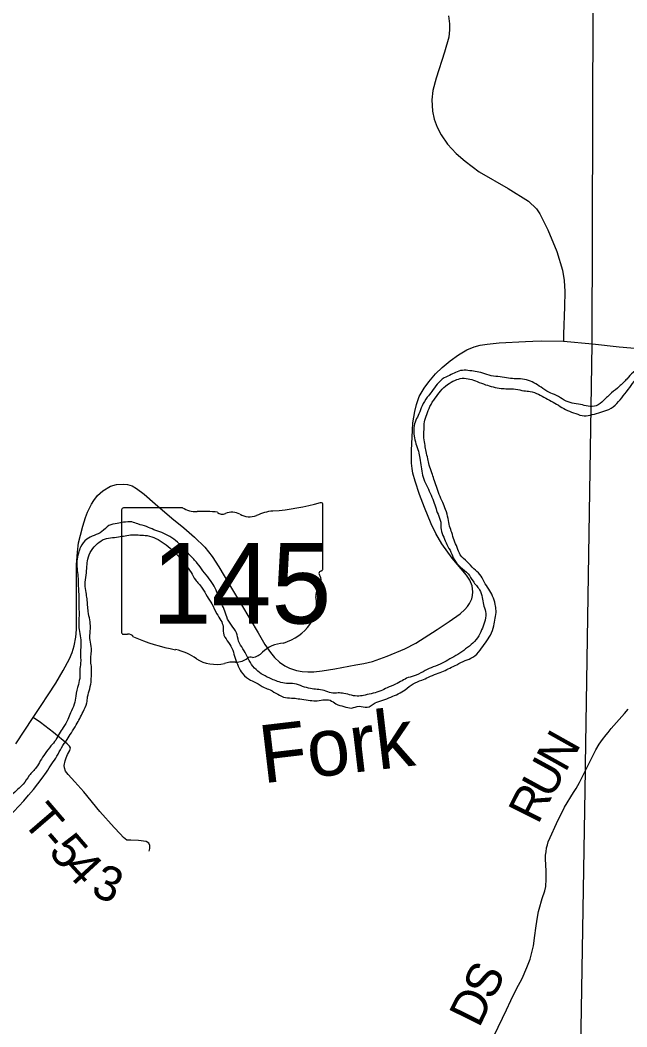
# Model space of a CAD drawing. Extents: x -10.5 to 40.6, y -3.2 to 22.
# Drawn here: x -7.105 to -6.111, y 17.758 to 19.405 of the extents above; entities that cross this region are included whole.
import ezdxf

# ---------------------------------------------------------------- set-up
doc = ezdxf.new("R2010")
doc.units = 0
for name, color, linetype in [('GM_X_Major_River', 7, 'Continuous'), ('GM_X_Major_River_Text', 7, 'Continuous'), ('GM_X_State_Location', 7, 'Continuous'), ('GM_X_State_Route', 7, 'Continuous'), ('GM_X_State_Shield', 7, 'Continuous'), ('GM_X_Township_Road', 7, 'Continuous'), ('GM_X_Township_Road_Text', 7, 'Continuous'), ('GM_X_Township_Text', 7, 'Continuous')]:
    doc.layers.add(name, color=color, linetype=linetype)

msp = doc.modelspace()

# ---------------------------------------------------------------- linework, layer by layer
at = {"layer": 'GM_X_Major_River'}
for points in [[(-5.8589, 19.0727), (-5.8485, 19.0607), (-5.838, 19.0484), (-5.8313, 19.0356), (-5.8292, 19.0219), (-5.8305, 19.0098), (-5.8341, 18.9972), (-5.8411, 18.9845), (-5.8511, 18.9714), (-5.863, 18.9602), (-5.8761, 18.9474), (-5.8891, 18.9358), (-5.8989, 18.9273), (-5.9104, 18.9168), (-5.922, 18.9052), (-5.934, 18.8952), (-5.9471, 18.887), (-5.9602, 18.8784), (-5.9734, 18.8706), (-5.9858, 18.865), (-5.9982, 18.8599), (-6.0111, 18.8577), (-6.0258, 18.8529), (-6.0386, 18.85), (-6.0503, 18.8479), (-6.0628, 18.8458), (-6.0757, 18.8426), (-6.0873, 18.8374), (-6.1008, 18.8285), (-6.1113, 18.8176), (-6.1236, 18.8053), (-6.1363, 18.7948), (-6.1493, 18.7824), (-6.1613, 18.7739), (-6.1746, 18.7729), (-6.1872, 18.7761), (-6.2009, 18.7781), (-6.2138, 18.7832), (-6.2265, 18.7906), (-6.2391, 18.7961), (-6.2518, 18.8042), (-6.2633, 18.8112), (-6.2755, 18.8163), (-6.2888, 18.818), (-6.2983, 18.8182), (-6.3116, 18.8203), (-6.326, 18.8219), (-6.3405, 18.8247), (-6.3535, 18.829), (-6.3653, 18.8307), (-6.3774, 18.832), (-6.3891, 18.8295), (-6.3989, 18.8248), (-6.4102, 18.8193), (-6.4218, 18.8092), (-6.4303, 18.7973), (-6.4381, 18.7877), (-6.4466, 18.7739), (-6.4517, 18.7605), (-6.4568, 18.7501), (-6.46, 18.7379), (-6.4594, 18.7243), (-6.4565, 18.7118), (-6.4525, 18.6993), (-6.4504, 18.688), (-6.4479, 18.6739), (-6.4458, 18.6603), (-6.441, 18.6471), (-6.4347, 18.6343), (-6.4291, 18.6211), (-6.4247, 18.6083), (-6.4204, 18.5962), (-6.416, 18.5833), (-6.4154, 18.5712), (-6.411, 18.5587), (-6.4058, 18.5467), (-6.3992, 18.5343), (-6.394, 18.5222), (-6.3836, 18.5098), (-6.3712, 18.4987), (-6.3631, 18.4867), (-6.3526, 18.4728), (-6.3482, 18.4603), (-6.3461, 18.4486), (-6.3425, 18.4373), (-6.3434, 18.4232), (-6.3477, 18.4102), (-6.3536, 18.3976), (-6.3632, 18.3856), (-6.3752, 18.3759), (-6.3879, 18.367), (-6.4011, 18.3595), (-6.4135, 18.3525), (-6.4281, 18.3465), (-6.4413, 18.3406), (-6.456, 18.3331), (-6.4692, 18.3291)], [(-6.4358, 18.3297), (-6.423, 18.3352), (-6.4113, 18.3396), (-6.4012, 18.3447), (-6.3895, 18.3502), (-6.376, 18.3569), (-6.3636, 18.3624), (-6.3512, 18.3741), (-6.3427, 18.386), (-6.3346, 18.3987), (-6.3292, 18.4139), (-6.3267, 18.4261), (-6.3254, 18.4387), (-6.3268, 18.4489), (-6.3312, 18.4625), (-6.3374, 18.4738), (-6.3448, 18.4858), (-6.3519, 18.4979), (-6.3619, 18.5072), (-6.3727, 18.5184), (-6.3839, 18.53), (-6.3891, 18.542), (-6.3942, 18.5537), (-6.3978, 18.5662), (-6.4014, 18.5768), (-6.4039, 18.5892), (-6.408, 18.604), (-6.4127, 18.6157), (-6.4183, 18.6289), (-6.4231, 18.6417), (-6.4271, 18.6538), (-6.4303, 18.664), (-6.435, 18.6768), (-6.4371, 18.687), (-6.44, 18.6991), (-6.4417, 18.709), (-6.4434, 18.7211), (-6.4433, 18.7348), (-6.4427, 18.7473), (-6.4388, 18.7596), (-6.4337, 18.7726), (-6.4252, 18.786), (-6.4163, 18.7979), (-6.4051, 18.8084), (-6.3927, 18.8154), (-6.381, 18.8187), (-6.3681, 18.8174), (-6.3562, 18.8134), (-6.3425, 18.8083), (-6.3303, 18.8047), (-6.317, 18.8023), (-6.3067, 18.8017), (-6.2934, 18.8012), (-6.2797, 18.7984), (-6.2695, 18.7971), (-6.2561, 18.7927), (-6.2439, 18.7861), (-6.232, 18.7799), (-6.2205, 18.7728), (-6.2086, 18.7662), (-6.1949, 18.7611), (-6.1812, 18.7572), (-6.1679, 18.7593), (-6.1539, 18.7634), (-6.1407, 18.7678), (-6.1276, 18.7775), (-6.1172, 18.7902), (-6.1065, 18.8037), (-6.0968, 18.8168), (-6.083, 18.8254), (-6.058, 18.8288), (-6.0425, 18.834), (-6.0293, 18.8377), (-6.0157, 18.8421), (-6.0056, 18.8464), (-5.9916, 18.8501), (-5.9814, 18.8533), (-5.9682, 18.8589), (-5.9554, 18.8655), (-5.9431, 18.8734), (-5.9292, 18.882), (-5.9168, 18.8913), (-5.9083, 18.9009), (-5.8952, 18.9125), (-5.8828, 18.9226), (-5.8694, 18.9354), (-5.8571, 18.947), (-5.8455, 18.959), (-5.8355, 18.9717), (-5.8282, 18.9851), (-5.8216, 18.9981), (-5.818, 19.01), (-5.8175, 19.0229), (-5.82, 19.0358), (-5.8255, 19.0486), (-5.8325, 19.0602), (-5.8426, 19.0722)], [(-6.4692, 18.3291), (-6.4793, 18.324), (-6.4902, 18.3181), (-6.5038, 18.3122), (-6.514, 18.3074), (-6.5268, 18.3034), (-6.5396, 18.3005), (-6.5498, 18.2988), (-6.562, 18.3001), (-6.5746, 18.3033), (-6.5841, 18.3039), (-6.5951, 18.3041), (-6.6069, 18.3077), (-6.6183, 18.3098), (-6.6293, 18.3111), (-6.6423, 18.3147), (-6.6556, 18.319), (-6.6686, 18.3196), (-6.6807, 18.322), (-6.6903, 18.3256), (-6.7156, 18.3396), (-6.7256, 18.3505), (-6.733, 18.3636), (-6.7397, 18.3761), (-6.7468, 18.3888), (-6.7504, 18.4021), (-6.7586, 18.4148), (-6.7664, 18.4284), (-6.7704, 18.4405), (-6.7759, 18.4525), (-6.7811, 18.4657), (-6.787, 18.4785), (-6.7948, 18.4906), (-6.8053, 18.5037), (-6.8146, 18.5164), (-6.8266, 18.5291), (-6.8366, 18.5381), (-6.8471, 18.5508), (-6.8597, 18.5597), (-6.8724, 18.5663), (-6.8854, 18.571), (-6.8976, 18.5761), (-6.9117, 18.5804), (-6.9216, 18.5837), (-6.9353, 18.5831), (-6.9455, 18.5814), (-6.9591, 18.5777), (-6.9707, 18.568), (-6.9834, 18.5617), (-6.9955, 18.5554), (-7.0055, 18.5424), (-7.0091, 18.5328), (-7.0115, 18.5198), (-7.0113, 18.5073), (-7.01, 18.4944), (-7.0094, 18.4819), (-7.0088, 18.469), (-7.0082, 18.4565), (-7.0083, 18.4443), (-7.0081, 18.4299), (-7.0086, 18.417), (-7.0073, 18.4045), (-7.0051, 18.3908), (-7.0053, 18.3779), (-7.0058, 18.3657), (-7.0053, 18.3563), (-7.0066, 18.3437), (-7.0067, 18.3312), (-7.0092, 18.3178), (-7.0134, 18.2988), (-7.0158, 18.2854), (-7.022, 18.2713), (-7.0264, 18.2606), (-7.0341, 18.2475), (-7.0408, 18.2371), (-7.0463, 18.2268), (-7.0541, 18.2172), (-7.0637, 18.2048), (-7.0715, 18.1926), (-7.0781, 18.1822), (-7.0896, 18.1687), (-7.0996, 18.1548), (-7.1134, 18.1417), (-7.125, 18.1301), (-7.1358, 18.12), (-7.1447, 18.1074), (-7.1536, 18.0973), (-7.1667, 18.0849), (-7.1783, 18.0737), (-7.1906, 18.061)], [(-7.1956, 18.0366), (-7.0613, 18.1745), (-7.0524, 18.1879), (-7.0443, 18.2006), (-7.0366, 18.2144), (-7.0277, 18.2279), (-7.0207, 18.2386), (-7.0126, 18.2517), (-7.0016, 18.2731), (-6.9954, 18.2877), (-6.994, 18.2976), (-6.9905, 18.3109), (-6.9881, 18.3254), (-6.9878, 18.3357), (-6.9876, 18.3452), (-6.9889, 18.355), (-6.9884, 18.3668), (-6.9878, 18.3767), (-6.9899, 18.3903), (-6.9901, 18.4013), (-6.9895, 18.4108), (-6.9905, 18.4237), (-6.993, 18.437), (-6.994, 18.4476), (-6.9949, 18.4578), (-6.9966, 18.4684), (-6.998, 18.4813), (-6.9964, 18.4969), (-6.9951, 18.511), (-6.9938, 18.5228), (-6.9876, 18.537), (-6.9779, 18.5482), (-6.9663, 18.5556), (-6.9534, 18.5581), (-6.9405, 18.5598), (-6.9296, 18.5615), (-6.9182, 18.5629), (-6.9087, 18.5623), (-6.8966, 18.5613), (-6.8821, 18.5566), (-6.869, 18.5485), (-6.856, 18.5381), (-6.8455, 18.5277), (-6.8351, 18.5145), (-6.8246, 18.5011), (-6.8175, 18.489), (-6.8063, 18.4755), (-6.7985, 18.462), (-6.7907, 18.4496), (-6.7828, 18.4338), (-6.7758, 18.4225), (-6.7722, 18.4127), (-6.7717, 18.4021), (-6.7654, 18.3893), (-6.7579, 18.3773), (-6.7535, 18.364), (-6.7488, 18.3508), (-6.7425, 18.3384), (-6.7305, 18.3268), (-6.7183, 18.3206), (-6.7049, 18.3129), (-6.6953, 18.3088), (-6.67, 18.2964), (-6.6571, 18.2955), (-6.6469, 18.2941), (-6.6328, 18.2921), (-6.621, 18.2911), (-6.6089, 18.2925), (-6.5971, 18.2919), (-6.5876, 18.286), (-6.5746, 18.2817), (-6.562, 18.2793), (-6.5496, 18.2821), (-6.5366, 18.2805), (-6.5235, 18.2875), (-6.511, 18.2919), (-6.4975, 18.2971), (-6.4742, 18.3093), (-6.4611, 18.319), (-6.4471, 18.3249), (-6.4358, 18.3297)]]:
    msp.add_spline(points, degree=3, dxfattribs=at)
at = {"layer": 'GM_X_State_Route'}
for points in [[(-6.4035, 19.4118), (-6.4014, 19.3986), (-6.4014, 19.3891), (-6.4029, 19.3769), (-6.4099, 19.3525), (-6.4237, 19.3096), (-6.4288, 19.2894), (-6.4303, 19.2746), (-6.4296, 19.2557), (-6.4268, 19.2426), (-6.422, 19.2299), (-6.4153, 19.2172), (-6.4049, 19.2017), (-6.3906, 19.1865), (-6.3759, 19.1739), (-6.3532, 19.1565), (-6.3056, 19.1293), (-6.2723, 19.1084), (-6.2594, 19.096), (-6.2537, 19.0881), (-6.2488, 19.078), (-6.2406, 19.0616), (-6.2261, 19.0262), (-6.2169, 18.9957), (-6.2141, 18.9786), (-6.2127, 18.9608), (-6.2133, 18.9358), (-6.2149, 18.8907), (-6.2151, 18.8795)], [(-6.2151, 18.8795), (-6.1676, 18.875), (-6.1239, 18.8703), (-6.1049, 18.8687), (-6.0917, 18.868), (-6.0781, 18.8683), (-6.0676, 18.8699), (-6.0607, 18.8715), (-6.053, 18.874), (-6.0416, 18.8797), (-6.0326, 18.8851), (-6.0226, 18.8927), (-6.0091, 18.9037), (-6, 18.9114)], [(-7.1116, 18.2209), (-7.0832, 18.2636), (-7.0703, 18.2834), (-7.0588, 18.3008), (-7.046, 18.3202), (-7.0338, 18.3408), (-7.0237, 18.36), (-7.0196, 18.37), (-7.0159, 18.3811), (-7.0133, 18.3953), (-7.0122, 18.408), (-7.0124, 18.4211), (-7.0121, 18.439), (-7.0124, 18.4836), (-7.0124, 18.4979), (-7.0121, 18.5133), (-7.0107, 18.5343), (-7.0087, 18.5496), (-7.0059, 18.5622), (-7.0021, 18.5768), (-6.9974, 18.591), (-6.9941, 18.5996), (-6.9876, 18.613), (-6.984, 18.6189), (-6.978, 18.627), (-6.9689, 18.6348), (-6.9567, 18.6421), (-6.9465, 18.6448), (-6.9351, 18.6457), (-6.9286, 18.6449), (-6.9212, 18.6427), (-6.914, 18.6386), (-6.9013, 18.6291), (-6.8836, 18.6133), (-6.8562, 18.5901), (-6.8366, 18.5739), (-6.8192, 18.559), (-6.802, 18.5423), (-6.7902, 18.5274), (-6.7795, 18.5102), (-6.7634, 18.4833), (-6.7423, 18.4482), (-6.7151, 18.4022), (-6.7037, 18.383), (-6.6948, 18.3702), (-6.6883, 18.3621), (-6.6798, 18.3543), (-6.6713, 18.3484), (-6.6636, 18.3444), (-6.6521, 18.3405), (-6.6427, 18.3391), (-6.6333, 18.3383), (-6.6236, 18.3384), (-6.6102, 18.34), (-6.5896, 18.3432), (-6.5547, 18.3498), (-6.542, 18.3522), (-6.5277, 18.3556), (-6.5038, 18.3639), (-6.4748, 18.376), (-6.4569, 18.3853), (-6.4218, 18.4077), (-6.4024, 18.4208), (-6.3843, 18.4335), (-6.3763, 18.4407), (-6.372, 18.4452), (-6.3689, 18.4501), (-6.365, 18.4578), (-6.3637, 18.4633), (-6.3632, 18.4696), (-6.3645, 18.4793), (-6.3684, 18.4887), (-6.3739, 18.4965), (-6.3973, 18.5247), (-6.4143, 18.5478), (-6.4241, 18.565), (-6.4318, 18.5805), (-6.4428, 18.6076), (-6.4507, 18.6286), (-6.4579, 18.6505), (-6.4615, 18.6634), (-6.4629, 18.6713), (-6.4639, 18.68), (-6.4639, 18.6871), (-6.4637, 18.7012), (-6.4624, 18.7336), (-6.4614, 18.746), (-6.4586, 18.7643), (-6.4557, 18.7759), (-6.4513, 18.7889), (-6.4433, 18.8028), (-6.4356, 18.8131), (-6.4244, 18.8261), (-6.4137, 18.8362), (-6.4007, 18.8473), (-6.3867, 18.8572), (-6.3732, 18.8651), (-6.3612, 18.87), (-6.3512, 18.8731), (-6.3401, 18.8748), (-6.3202, 18.8768), (-6.2773, 18.8789), (-6.2653, 18.8794)], [(-6.2653, 18.8794), (-6.2504, 18.88), (-6.2151, 18.8795)]]:
    msp.add_lwpolyline(points, dxfattribs=at)
at = {"layer": 'GM_X_State_Shield'}
for p, q in [((-6.9384, 18.6035), (-6.9384, 18.4034)), ((-6.8386, 18.6069), (-6.9351, 18.6069)), ((-6.6088, 18.5072), (-6.6088, 18.6119)), ((-6.6088, 18.5072), (-6.6088, 18.5072))]:
    msp.add_line(p, q, dxfattribs=at)
for centre, major_axis, start_param, end_param in [((-6.7262, 18.8798), (0.3495, 0), 4.814394, 5.042369), ((-6.6124, 18.6123), (0.00367, 0), 6.141152, 7.989035), ((-6.9346, 18.6039), (0.00382, 0), 1.712693, 3.28349), ((-6.8156, 18.6302), (0.037, 0), 4.042523, 4.731795), ((-6.8033, 18.4946), (0.133, 0), 1.404758, 1.657858), ((-6.7731, 18.6049), (0.0107, 0), 3.836095, 5.185415), ((-6.7575, 18.5818), (0.0222, 0), 0.950623, 2.079405), ((-6.6816, 18.5458), (0.0703, 0), 1.699011, 2.107814), ((-6.7288, 18.6135), (0.0267, 0), 4.081561, 5.145723), ((-6.6096, 18.4995), (0.00568, 0), 1.883978, 3.671073), ((-6.6127, 18.5068), (0.00393, 0), 5.05454, 6.418171), ((-6.6457, 18.4863), (0.0341, 0), 5.934695, 6.695948), ((-6.5956, 18.4634), (0.0248, 0), 2.387724, 3.262537), ((-6.7066, 18.4501), (0.0874, 0), 5.101752, 6.440018), ((-6.9346, 18.4029), (0.00385, 0), 3.00124, 4.508301), ((-6.934, 18.4234), (0.0294, 0), 4.665946, 4.897461), ((-6.928, 18.3918), (0.0106, 0), 0.519207, 1.627899), ((-6.7941, 18.5716), (0.2524, 0), 4.195997, 4.488961), ((-6.6697, 18.3472), (0.0479, 0), 1.647645, 2.488434), ((-6.8694, 18.3135), (0.079, 0), 0.823519, 1.323587), ((-6.7304, 18.384), (0.0282, 0), 4.937069, 5.64225), ((-6.784, 18.3908), (0.0501, 0), 4.026481, 4.996735), ((-6.755, 18.3216), (0.0412, 0), 1.495662, 1.94098), ((-6.7513, 18.3758), (0.0267, 0), 4.691044, 5.507374), ((-6.7272, 18.3565), (0.00752, 0), 1.147584, 2.315152)]:
    msp.add_ellipse(centre, major_axis=major_axis, ratio=0.8, start_param=start_param, end_param=end_param, dxfattribs=at)
at = {"layer": 'GM_X_Township_Road'}
for points in [[(-6.1421, 18.2394), (-6.1367, 18.2455), (-6.1152, 18.2702), (-6.109, 18.2775)], [(-6.8932, 18.0452), (-6.8924, 18.0495), (-6.8923, 18.0546), (-6.8937, 18.0582), (-6.8983, 18.0607), (-6.9109, 18.0623), (-6.9233, 18.0633), (-6.9298, 18.0633), (-6.9354, 18.0673), (-6.9408, 18.0733), (-6.9506, 18.0839), (-6.9743, 18.1099), (-7.0005, 18.1419), (-7.0148, 18.1586), (-7.0261, 18.1706), (-7.03, 18.1761), (-7.032, 18.1812), (-7.0326, 18.1853), (-7.031, 18.1929), (-7.029, 18.1978), (-7.027, 18.2035), (-7.0232, 18.2096), (-7.0222, 18.214), (-7.0239, 18.2168), (-7.0277, 18.2208), (-7.0501, 18.2391), (-7.0714, 18.2558), (-7.0832, 18.2636)], [(-6.3285, 17.7433), (-6.3082, 17.7853), (-6.301, 17.8005), (-6.2918, 17.8196), (-6.2828, 17.8369), (-6.2748, 17.8547), (-6.2695, 17.8686), (-6.2641, 17.8902), (-6.2618, 17.9073), (-6.2604, 17.9191), (-6.2583, 17.9336), (-6.2558, 17.9461), (-6.2548, 17.95), (-6.2497, 17.9675), (-6.2454, 17.9803), (-6.244, 17.9875), (-6.2433, 17.9992), (-6.2434, 18.0131), (-6.244, 18.0223), (-6.2445, 18.0324), (-6.2443, 18.0383), (-6.2435, 18.0442), (-6.2426, 18.0506), (-6.2414, 18.0555), (-6.2399, 18.0603), (-6.2367, 18.0674), (-6.2263, 18.0901), (-6.2133, 18.1168), (-6.1984, 18.1408), (-6.194, 18.1478), (-6.1887, 18.1575), (-6.179, 18.1772), (-6.162, 18.2107), (-6.1565, 18.2202), (-6.1512, 18.2279), (-6.1454, 18.2356), (-6.1421, 18.2394)]]:
    msp.add_lwpolyline(points, dxfattribs=at)
at = {"layer": 'GM_X_Township_Text'}
msp.add_lwpolyline([(-6.192, 17.3965), (-6.1792, 18.1778), (-6.179, 18.1863), (-6.1678, 18.8746), (-6.1678, 18.8755), (-6.1618, 20.9), (-10.5445, 20.9), (-10.5445, 19.4241)], dxfattribs=at)

# ---------------------------------------------------------------- texts
at = {"layer": 'GM_X_Major_River_Text'}
msp.add_text('Fork', height=0.09469, rotation=6.7255, dxfattribs=at).set_placement((-6.7071, 18.1559))
at = {"layer": 'GM_X_State_Location'}
for s in ['s', 'r']:
    msp.add_text(s, height=0.000189, dxfattribs=at).set_placement((-6.7773, 18.4901))
msp.add_text('145', height=0.000189, rotation=0, dxfattribs=at).set_placement((-6.8441, 18.4763))
at = {"layer": 'GM_X_State_Shield'}
msp.add_text('145', height=0.13184, dxfattribs=at).set_placement((-6.8892, 18.4175))
at = {"layer": 'GM_X_Township_Road_Text'}
for s, rotation, p in [('N', 60.7214, (-6.2121, 18.1724)), ('U', 61.3264, (-6.236, 18.1286)), ('R', 63.2342, (-6.2568, 18.0874)), ('T', 310.6534, (-7.1029, 18.0933)), ('-', 310.6905, (-7.0752, 18.0611)), ('5', 310.8418, (-7.0598, 18.0433)), ('4', 312.5472, (-7.0357, 18.0154)), ('3', 336.7839, (-6.9908, 17.9746)), ('S', 63.7332, (-6.3312, 17.7995)), ('D', 63.6956, (-6.3534, 17.7546))]:
    msp.add_text(s, height=0.0568, rotation=rotation, dxfattribs=at).set_placement(p)

doc.saveas('drawing.dxf')
